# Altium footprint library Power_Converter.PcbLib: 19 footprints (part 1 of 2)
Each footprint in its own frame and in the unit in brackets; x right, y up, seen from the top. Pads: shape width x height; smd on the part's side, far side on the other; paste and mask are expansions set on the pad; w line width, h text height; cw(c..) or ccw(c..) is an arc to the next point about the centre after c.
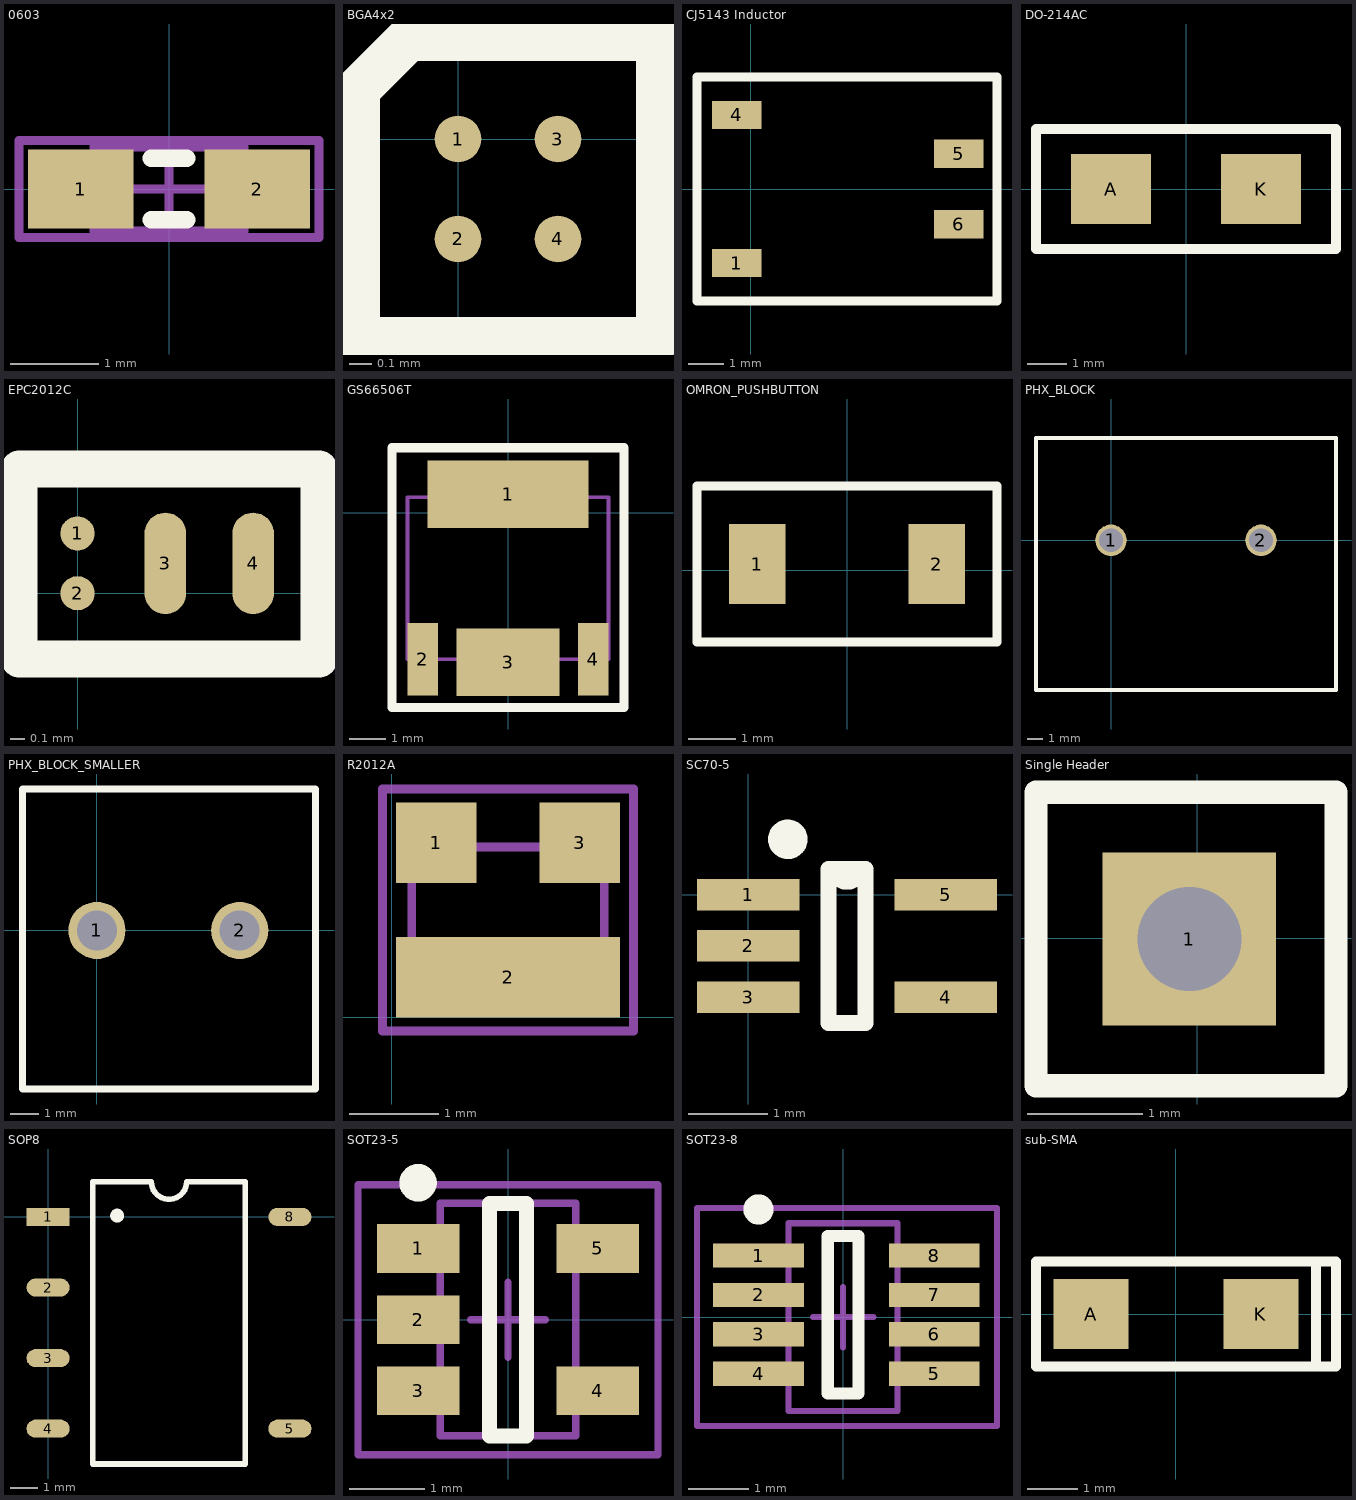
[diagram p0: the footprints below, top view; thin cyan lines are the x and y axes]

## 0603 [mm]
pads (2):
  rect 1.2x0.9 smd: 1(-1,0) 2(1,0)
Top Overlay:
  lines w0.2: -0.2,-0.35 0.2,-0.35 ; -0.2,0.35 0.2,0.35
Mechanical 13:
  lines w0.1: -0.85,-0.475 -0.85,0.475 0.85,0.475 0.85,-0.475 -0.85,-0.475
Mechanical 15:
  lines w0.1: -0.475,0 0.475,0 ; 0,-0.475 0,0.475 ; -1.7,-0.55 -1.7,0.55 1.7,0.55 1.7,-0.55 -1.7,-0.55
3D body: height 0.9, standoff 0, extent -0.85,-0.475 0.85,0.475

## BGA4x2 [mm]
pads (4):
  round 0.21 smd: 1(0,0) 2(0,-0.45) 3(0.45,0) 4(0.45,-0.45)
Top Overlay:
  lines w0.2: -0.45,-0.9 0.9,-0.9 0.9,0.45 -0.225,0.45 -0.45,0.225 -0.45,-0.9

## CJ5143 Inductor [mm]
pads (4):
  rect 1.4x0.8 smd: 1(-0.4,-2.1) 4(-0.4,2.1) 5(5.9,1) 6(5.9,-1)
Top Overlay:
  lines w0.254: -1.524,-3.175 6.985,-3.175 6.985,3.175 -1.524,3.175 -1.524,-3.175

## DO-214AC [mil]
pads (2):
  rect 80x70 smd: A(-75,0) K(75,0)
Top Overlay:
  lines w10: -150,-60 -150,0 -150,60 150,60 150,-60 -150,-60

## EPC2012C [mm]
pads (4):
  round 0.234 smd mask+0.01: 1(0,0.409) 2(0,0)
  oval 0.284x0.693 smd mask-0.025: 3(0.6,0.205) 4(1.2,0.205)
Top Overlay:
  lines w0.254: -0.4,-0.45 -0.4,0.85 1.65,0.85 1.65,-0.45 -0.4,-0.45

## GS66506T [mm]
pads (4):
  rect 4.4x1.84 smd: 1(0,0.5)
  rect 0.84x1.99 smd: 2(-2.33,-4.02) 4(2.33,-4.02)
  rect 2.83x1.84 smd: 3(0,-4.1)
Top Overlay:
  lines w0.254: -3.175,-5.334 -3.175,1.778 3.175,1.778 3.175,-5.334 -3.175,-5.334
Mechanical 13:
  lines w0.1: -2.75,-4.02 -2.75,0.42 2.75,0.42 2.75,-4.02 -2.75,-4.02

## OMRON_PUSHBUTTON [mm]
pads (2):
  rect 1.2x1.7 smd: 1(-1.9,0.127) 2(1.9,0.127)
Top Overlay:
  lines w0.2: -3.175,-1.524 3.175,-1.524 3.175,1.778 -3.175,1.778 -3.175,-1.524

## PHX_BLOCK [mm]
pads (2):
  round 2 hole 1.5: 1(0,0) 2(9.52,0)
Top Overlay:
  lines w0.254: -4.76,-9.5 -4.76,6.5 14.28,6.5 14.28,-9.5 -4.76,-9.5

## PHX_BLOCK_SMALLER [mm]
pads (2):
  round 2 hole 1.4: 1(0,0) 2(5,0)
Top Overlay:
  lines w0.254: -2.6,-5.55 7.65,-5.55 7.65,4.95 -2.6,4.95 -2.6,-5.55

## R2012A [mm] "Voltage Divider 0805 Footprint"
pads (3):
  rect 0.9x0.9 smd: 1(0.5,1.95) 3(2.1,1.95)
  rect 2.5x0.9 smd: 2(1.3,0.45)
Mechanical 13:
  lines w0.1: 0.225,0.5 0.225,1.9 2.375,1.9 2.375,0.5 0.225,0.5
Mechanical 15:
  lines w0.1: -0.1,-0.15 2.7,-0.15 2.7,2.55 -0.1,2.55 -0.1,-0.15
3D body: height 0.7, standoff 0, extent 0.225,0.5 2.375,1.9

## SC70-5 [mm]
pads (5):
  rect 1.3x0.4 smd: 1(0,0) 2(0,-0.65) 3(0,-1.3) 4(2.5,-1.3) 5(2.5,0)
Top Overlay:
  circle w0.25: c0.5,0.7 r0.125
  lines w0.2: 1.015,-1.625 1.015,0.325 1.412,0.325 cw(c1.25,0.325) 1.088,0.325 1.485,0.325 1.485,-1.625 1.015,-1.625

## Single Header [mm]
pads (1):
  rect 1.5x1.5 hole 0.9: 1(-0.07,-0.008)
Top Overlay:
  lines w0.2: -1.397,-1.278 1.2,-1.278 1.2,1.262 -1.397,1.262 -1.397,-1.278

## SOP8 [mm]
pads (6):
  rect 1.55x0.65 smd: 1(0,0)
  oval 1.55x0.65 smd: 2(0,-2.54) 3(0,-5.08) 4(0,-7.62) 5(8.7,-7.62) 8(8.7,0)
Top Overlay:
  circle w0.25: c2.483,0.047 r0.125
  lines w0.2: 1.61,-8.89 1.61,1.27 3.715,1.27 ccw(c4.35,1.27) 4.985,1.27 7.09,1.27 7.09,-8.89 1.61,-8.89

## SOT23-5 [mm]
pads (5):
  rect 1.1x0.65 smd: 1(-1.2,0.95) 2(-1.2,0) 3(-1.2,-0.95) 4(1.2,-0.95) 5(1.2,0.95)
Top Overlay:
  circle w0.25: c-1.2,1.825 r0.125
  lines w0.2: -0.25,-1.55 0.25,-1.55 0.25,1.55 -0.25,1.55 -0.25,-1.55
Mechanical 13:
  lines w0.1: -0.9,-1.55 -0.9,1.55 0.9,1.55 0.9,-1.55 -0.9,-1.55
Mechanical 15:
  lines w0.1: -0.5,0 0.5,0 ; 0,-0.5 0,0.5 ; -2,-1.8 -2,1.8 2,1.8 2,-1.8 -2,-1.8
3D body: height 1.45, standoff 0, extent -0.9,-1.55 0.9,1.55

## SOT23-8 [mm]
pads (8):
  rect 1.5x0.4 smd: 1(-1.397,1.016) 2(-1.397,0.366) 3(-1.397,-0.284) 4(-1.397,-0.934) 5(1.503,-0.934) 6(1.503,-0.284) 7(1.503,0.366) 8(1.503,1.016)
Top Overlay:
  circle w0.25: c-1.397,1.778 r0.125
  lines w0.2: -0.109,1.341 0.254,1.341 0.254,-1.259 -0.254,-1.259 -0.254,1.341 0.215,1.341
Mechanical 13:
  lines w0.1: -0.9,-1.55 -0.9,1.55 0.9,1.55 0.9,-1.55 -0.9,-1.55
Mechanical 15:
  lines w0.1: -0.5,0 0.5,0 ; 0,-0.5 0,0.5 ; -2.413,-1.8 -2.413,1.8 2.54,1.8 2.54,-1.8 -2.413,-1.8
3D body: height 1.45, standoff 0, extent -0.9,-1.55 0.9,1.55

## sub-SMA [mm]
pads (2):
  rect 1.5x1.4 smd: A(-1.7,0) K(1.7,0)
Top Overlay:
  lines w0.2: 2.8,-1.05 2.8,1.05 ; -2.8,-1.05 3.2,-1.05 3.2,1.05 -2.8,1.05 -2.8,-1.05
